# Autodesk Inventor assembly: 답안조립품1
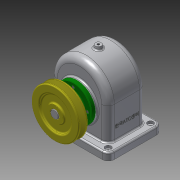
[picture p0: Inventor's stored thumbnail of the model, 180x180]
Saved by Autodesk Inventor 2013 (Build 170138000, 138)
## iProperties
Created: 2016-10
Part Number: 답안조립품1
Document SubType Name: Assembly
Designer: Administrator
Author: Administrator
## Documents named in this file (15)
- C:\Users\Administrator\Desktop\461007V1013\답안조립품1.iam
- C:\Users\Administrator\Desktop\461007V1013\본체.ipt
- C:\Users\Administrator\Desktop\461007V1013\V-벨트풀리.ipt
- C:\Users\Administrator\Desktop\461007V1013\뒤커버.ipt
- C:\Users\Administrator\Desktop\461007V1013\멈춤나사 - M4x10.ipt
- C:\Users\Administrator\Desktop\461007V1013\베어링 6203.ipt
- C:\Users\Administrator\Desktop\461007V1013\볼트 M3 x 8.ipt
- C:\Users\Administrator\Desktop\461007V1013\볼트 M3 x 10.ipt
- C:\Users\Administrator\Desktop\461007V1013\부시.ipt
- C:\Users\Administrator\Desktop\461007V1013\스퍼기어.ipt
- C:\Users\Administrator\Desktop\461007V1013\앞커버.ipt
- C:\Users\Administrator\Desktop\461007V1013\오일씰 28 40 8.ipt
- C:\Users\Administrator\Desktop\461007V1013\축.ipt
- C:\Users\Administrator\Desktop\461007V1013\키 - 5 x 5 x 18.ipt
- C:\Users\Administrator\Desktop\461007V1013\키 - 6 x 6 x 22.ipt
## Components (9 placed, 3 different names)
1. V-벨트풀리:1
2. ISO 4762 M3 x 10:1
3. ISO 4762 M3 x 10:2
4. ISO 4762 M3 x 10:3
5. ISO 4762 M3 x 10:4
6. ISO 4762 M3 x 8:1
7. ISO 4762 M3 x 8:2
8. ISO 4762 M3 x 8:3
9. ISO 4762 M3 x 8:4
